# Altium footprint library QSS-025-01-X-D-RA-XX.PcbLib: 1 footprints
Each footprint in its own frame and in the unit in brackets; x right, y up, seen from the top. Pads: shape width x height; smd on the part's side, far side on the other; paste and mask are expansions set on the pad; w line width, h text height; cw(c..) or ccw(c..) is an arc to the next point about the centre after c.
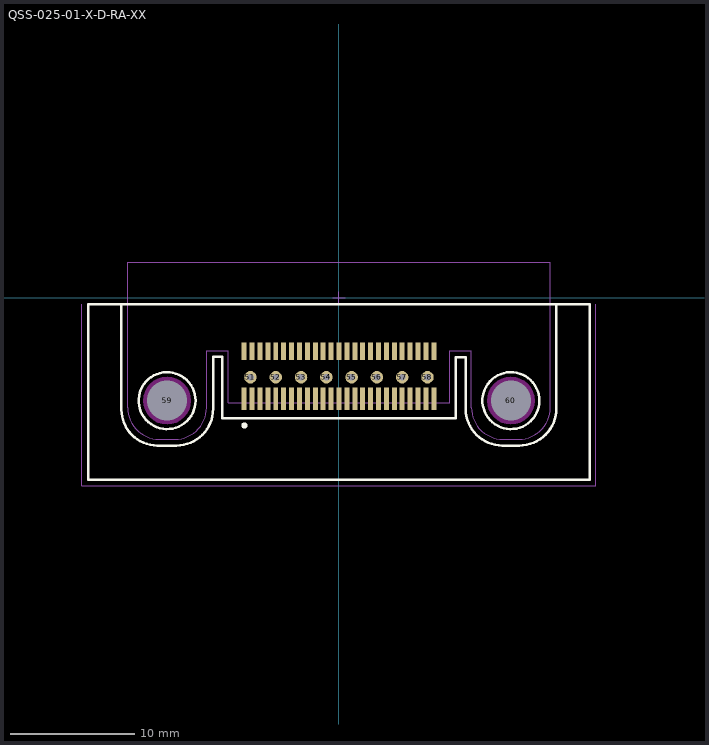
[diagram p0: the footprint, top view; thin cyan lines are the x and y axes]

## QSS-025-01-X-D-RA-XX [mm] "0.635mm pitch, 50 pin, high speed socket strip; r/a"
height 8.33
pads (60):
  rect 0.4x1.8 smd mask+0: 1(-7.62,-8.103) 3(-6.985,-8.103) 5(-6.35,-8.103) 7(-5.715,-8.103) 9(-5.08,-8.103) 11(-4.445,-8.103) 13(-3.81,-8.103) 15(-3.175,-8.103) 17(-2.54,-8.103) 19(-1.905,-8.103) 21(-1.27,-8.103) 23(-0.635,-8.103) 25(0,-8.103) 27(0.635,-8.103) 29(1.27,-8.103) 31(1.905,-8.103) 33(2.54,-8.103) 35(3.175,-8.103) 37(3.81,-8.103) 39(4.445,-8.103) 41(5.08,-8.103) 43(5.715,-8.103) 45(6.35,-8.103) 47(6.985,-8.103) 49(7.62,-8.103)
  rect 0.4x1.4 smd mask+0: 2(-7.62,-4.293) 4(-6.985,-4.293) 6(-6.35,-4.293) 8(-5.715,-4.293) 10(-5.08,-4.293) 12(-4.445,-4.293) 14(-3.81,-4.293) 16(-3.175,-4.293) 18(-2.54,-4.293) 20(-1.905,-4.293) 22(-1.27,-4.293) 24(-0.635,-4.293) 26(0,-4.293) 28(0.635,-4.293) 30(1.27,-4.293) 32(1.905,-4.293) 34(2.54,-4.293) 36(3.175,-4.293) 38(3.81,-4.293) 40(4.445,-4.293) 42(5.08,-4.293) 44(5.715,-4.293) 46(6.35,-4.293) 48(6.985,-4.293) 50(7.62,-4.293)
  round 1 hole 0.55 mask+0: 51(-7.112,-6.376) 52(-5.08,-6.376) 53(-3.048,-6.376) 54(-1.016,-6.376) 55(1.016,-6.376) 56(3.048,-6.376) 57(5.08,-6.376) 58(7.112,-6.376)
  round 1 hole 3.2 unplated mask+0: 59(-13.811,-8.255) 60(13.811,-8.255)
Top Overlay:
  circle w0.25: c-7.6,-10.25 r0.125
  circle w0.2: c13.811,-8.255 r2.286
  circle w0.2: c-13.811,-8.255 r2.286
  lines w0.2: -20.15,-14.6 -20.15,-0.508 20.15,-0.508 20.15,-14.6 -20.15,-14.6 ; -17.475,-8.979 ccw(c-14.592,-8.979) -14.592,-11.862 -13.056,-11.862 ccw(c-13.056,-8.915) -10.109,-8.915 -10.109,-4.724 -9.398,-4.724 -9.398,-9.652 9.398,-9.652 9.398,-4.75 10.185,-4.75 10.185,-8.918 ccw(c13.129,-8.918) 13.129,-11.862 14.487,-11.862 ccw(c14.487,-8.873) 17.475,-8.873 17.475,-0.508 -17.475,-0.508 -17.475,-8.979
Keep-Out Layer:
  pour cut-out: 15.72,-8.255 15.684,-7.883 15.575,-7.524 15.398,-7.194 15.161,-6.905 14.872,-6.668 14.542,-6.491 14.183,-6.382 13.811,-6.346 13.439,-6.382 13.08,-6.491 12.75,-6.668 12.461,-6.905 12.224,-7.194 12.047,-7.524 11.938,-7.883 11.902,-8.255 11.938,-8.627 12.047,-8.986 12.224,-9.316 12.461,-9.605 12.75,-9.842 13.08,-10.019 13.439,-10.128 13.811,-10.164 14.183,-10.128 14.542,-10.019 14.872,-9.842 15.161,-9.605 15.398,-9.316 15.575,-8.986 15.684,-8.627
  pour cut-out: -11.902,-8.255 -11.938,-7.883 -12.047,-7.524 -12.224,-7.194 -12.461,-6.905 -12.75,-6.668 -13.08,-6.491 -13.439,-6.382 -13.811,-6.346 -14.183,-6.382 -14.542,-6.491 -14.872,-6.668 -15.161,-6.905 -15.398,-7.194 -15.575,-7.524 -15.684,-7.883 -15.72,-8.255 -15.684,-8.627 -15.575,-8.986 -15.398,-9.316 -15.161,-9.605 -14.872,-9.842 -14.542,-10.019 -14.183,-10.128 -13.811,-10.164 -13.439,-10.128 -13.08,-10.019 -12.75,-9.842 -12.461,-9.605 -12.224,-9.316 -12.047,-8.986 -11.938,-8.627
Mechanical 12:
  lines w0.001: -20.15,-14.6 -20.15,-0.508 20.15,-0.508 20.15,-14.6 -20.15,-14.6
Mechanical 13:
  lines w0.1: -16.986,-8.814 ccw(c-14.446,-8.814) -14.446,-11.354 -13.176,-11.354 ccw(c-13.176,-8.814) -10.636,-8.814 -10.636,-4.242 -8.89,-4.242 -8.89,-8.433 8.89,-8.433 8.89,-4.242 10.636,-4.242 10.636,-8.814 ccw(c13.176,-8.814) 13.176,-11.354 14.446,-11.354 ccw(c14.446,-8.814) 16.986,-8.814 16.986,2.87 -16.986,2.87 -16.986,-8.814
  text ".Designator" at 0.254,0.254 h1.52
Mechanical 15:
  lines w0.05: -20.65,-0.5 -20.65,-15.1 20.65,-15.1 20.65,-0.5 ; -0.5,0 0.5,0 ; 0,-0.5 0,0.5
Drill Drawing:
  lines w0.01: -24.359,0 26.772,0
